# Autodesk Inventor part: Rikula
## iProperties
Created: 2010-03
Part Number: Rikula
Document SubType Name: Modeling
Designer: UR
Density: 1 g/cm^3
Author: UR
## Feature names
1. Käfig li Steg [Revolution]
2. Käfig li Kugel [Revolution]
3. Käfig li hohl [Revolution]
4. Käfig li außen [Fillet]
5. Käfig li innen [Fillet]
6. Käfig re Steg [Revolution]
7. Käfig re Kugel [Revolution]
8. Käfig re hohl [Revolution]
9. Käfig re außen [Fillet]
10. Käfig re innen [Fillet]
11. Käfig ringförmig [Revolution]
12. Wälzkörper [Revolution]
13. Runde Anordnung1 [Circular Pattern]
14. Außenring [Revolution]
15. Innenring [Revolution]
16. Rundung5 [Fillet]
